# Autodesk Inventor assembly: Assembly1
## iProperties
Created: 2005-03
Part Number: Assembly1
Document SubType Name: Assembly
Designer: CADCIM
Manufacturer: Standard
Standards Organization: Custom
Author: CADCIM
